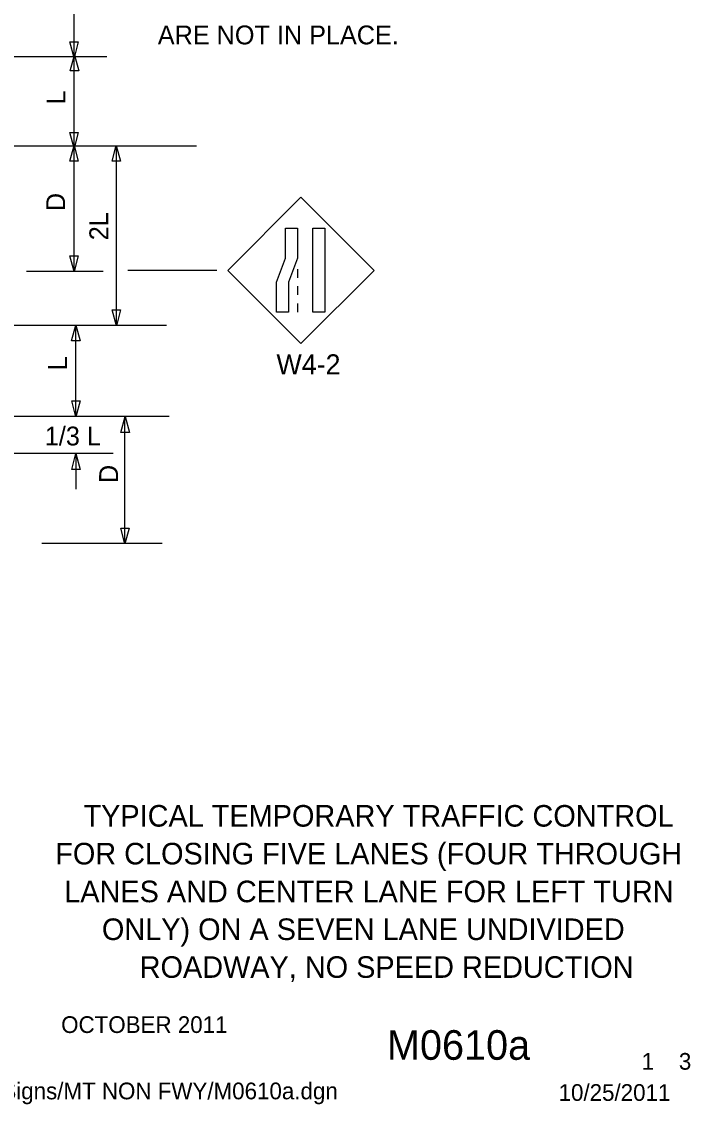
# Model space of a CAD drawing. Extents: x 16646 to 19498, y 2812 to 4437.
# Drawn here: x 17147.1 to 17395.3, y 3023.5 to 3425.5 of the extents above; entities that cross this region are included whole.
import ezdxf

# ---------------------------------------------------------------- set-up
doc = ezdxf.new("R2010")
doc.units = 0
for name, color, linetype in [('BORDER', 7, 'Continuous'), ('BORDER_SIGNAL_WO', 7, 'Continuous'), ('TRAFFIC_SIGNS_PR', 7, 'Continuous'), ('TYPICAL_TEXT_DIMEN_PR', 7, 'Continuous')]:
    doc.layers.add(name, color=color, linetype=linetype)

msp = doc.modelspace()

# ---------------------------------------------------------------- linework, layer by layer
at = {"layer": 'TRAFFIC_SIGNS_PR'}
for p, q in [((17250.74, 3360.24), (17223.58, 3333.09)), ((17277.89, 3333.09), (17250.74, 3360.24)), ((17223.58, 3333.09), (17250.74, 3305.93)), ((17249.49, 3333.58), (17249.49, 3330.38)), ((17250.74, 3305.93), (17277.89, 3333.09)), ((17249.49, 3327.18), (17249.49, 3323.98)), ((17249.49, 3320.78), (17249.49, 3317.58))]:
    msp.add_line(p, q, dxfattribs=at)
for points in [[(17249.49, 3348.82), (17249.49, 3337.64), (17246.14, 3328.76), (17246.14, 3317.58), (17241.65, 3317.58), (17241.65, 3328.76), (17244.99, 3337.64), (17244.99, 3348.82)], [(17259.62, 3348.82), (17259.62, 3317.58), (17255.13, 3317.58), (17255.13, 3348.82)]]:
    msp.add_lwpolyline(points, close=True, dxfattribs=at)
at = {"layer": 'TYPICAL_TEXT_DIMEN_PR'}
for p, q in [((17166.57, 3333.09), (17166.57, 3445.09)), ((17166.57, 3412.05), (17165, 3417.91)), ((17165, 3417.91), (17166.57, 3417.91)), ((17166.57, 3417.91), (17168.14, 3417.91)), ((17168.14, 3417.91), (17166.57, 3412.05)), ((17165.18, 3407.2), (17166.75, 3413.06)), ((17166.75, 3413.06), (17168.32, 3407.2)), ((17178.73, 3412.43), (17089.36, 3412.43)), ((17166.75, 3407.2), (17165.18, 3407.2)), ((17168.32, 3407.2), (17166.75, 3407.2)), ((17166.57, 3378.49), (17165, 3384.35)), ((17165, 3384.35), (17166.57, 3384.35)), ((17166.57, 3384.35), (17168.14, 3384.35)), ((17168.14, 3384.35), (17166.57, 3378.49)), ((17212.03, 3379.22), (17085.88, 3379.22)), ((17165, 3373.64), (17166.57, 3379.5)), ((17166.57, 3379.5), (17168.14, 3373.64)), ((17180.68, 3373.61), (17182.25, 3379.47)), ((17182.18, 3378.94), (17182.18, 3312.77)), ((17182.25, 3379.47), (17183.82, 3373.61)), ((17166.57, 3373.64), (17165, 3373.64)), ((17168.14, 3373.64), (17166.57, 3373.64)), ((17182.25, 3373.61), (17180.68, 3373.61)), ((17183.82, 3373.61), (17182.25, 3373.61)), ((17166.57, 3332.69), (17165, 3338.55)), ((17165, 3338.55), (17166.57, 3338.55)), ((17166.57, 3338.55), (17168.14, 3338.55)), ((17168.14, 3338.55), (17166.57, 3332.69)), ((17177.37, 3332.69), (17148.92, 3332.69)), ((17219.58, 3333.03), (17186.57, 3333.03)), ((17182.26, 3312.57), (17180.69, 3318.43)), ((17180.69, 3318.43), (17182.26, 3318.43)), ((17182.26, 3318.43), (17183.83, 3318.43)), ((17183.83, 3318.43), (17182.26, 3312.57)), ((17200.84, 3312.69), (17067.65, 3312.69)), ((17165.66, 3306.93), (17167.23, 3312.8)), ((17167.23, 3312.8), (17168.8, 3306.93)), ((17167.15, 3312.38), (17167.15, 3278.99)), ((17167.23, 3306.93), (17165.66, 3306.93)), ((17168.8, 3306.93), (17167.23, 3306.93)), ((17167.28, 3278.76), (17165.71, 3284.62)), ((17165.71, 3284.62), (17167.28, 3284.62)), ((17167.28, 3284.62), (17168.85, 3284.62)), ((17168.85, 3284.62), (17167.28, 3278.76)), ((17201.92, 3278.8), (17124.22, 3278.8)), ((17183.94, 3272.93), (17185.51, 3278.8)), ((17185.45, 3232.02), (17185.45, 3278.35)), ((17185.51, 3278.8), (17187.08, 3272.93)), ((17185.51, 3272.93), (17183.94, 3272.93)), ((17187.08, 3272.93), (17185.51, 3272.93)), ((17181.03, 3265.05), (17124.07, 3265.05)), ((17165.71, 3259.18), (17167.28, 3265.05)), ((17167.21, 3264.9), (17167.21, 3251.9)), ((17167.28, 3265.05), (17168.85, 3259.18)), ((17167.28, 3259.18), (17165.71, 3259.18)), ((17168.85, 3259.18), (17167.28, 3259.18)), ((17185.46, 3231.58), (17183.89, 3237.44)), ((17183.89, 3237.44), (17185.46, 3237.44)), ((17185.46, 3237.44), (17187.03, 3237.44)), ((17187.03, 3237.44), (17185.46, 3231.58)), ((17199.26, 3231.7), (17154.59, 3231.7))]:
    msp.add_line(p, q, dxfattribs=at)

# ---------------------------------------------------------------- texts
at = {"layer": 'BORDER'}
for s, p in [('TYPICAL TEMPORARY TRAFFIC CONTROL', (17170.08, 3126.58)), ('FOR CLOSING FIVE LANES (FOUR THROUGH', (17159.58, 3112.54)), ('LANES AND CENTER LANE FOR LEFT TURN', (17162.92, 3098.5)), ('ONLY) ON A SEVEN LANE UNDIVIDED', (17176.9, 3084.47)), ('ROADWAY, NO SPEED REDUCTION', (17190.92, 3070.43))]:
    msp.add_text(s, height=8.0099, dxfattribs=at).set_placement(p)
at = {"layer": 'BORDER_SIGNAL_WO'}
for s, height, p in [('    OCTOBER 2011    ', 6.2, (17152.56, 3049.96)), ('    M0610a   ', 11, (17266.34, 3040)), (' 1    3 ', 6.2, (17374.92, 3036.32)), ('PW RD/TS/Typicals/Signs/MT NON FWY/M0610a.dgn    ', 6.2, (17064.03, 3025.33)), ('10/25/2011    ', 6.2, (17346.4, 3024.75))]:
    msp.add_text(s, height=height, dxfattribs=at).set_placement(p)
at = {"layer": 'TRAFFIC_SIGNS_PR'}
for s, height, p in [('ARE NOT IN PLACE.', 7, (17197.64, 3417.01)), ('W4-2', 7.44, (17241.69, 3294.49))]:
    msp.add_text(s, height=height, dxfattribs=at).set_placement(p)
at = {"layer": 'TYPICAL_TEXT_DIMEN_PR'}
for s, p in [('L', (17163.35, 3394.71)), ('D', (17163.25, 3355.1)), ('2L', (17179.25, 3344.28)), ('L', (17163.95, 3296.01)), ('D', (17182.88, 3254.14))]:
    msp.add_text(s, height=7, rotation=90, dxfattribs=at).set_placement(p)
msp.add_text('1/3 L', height=7, dxfattribs=at).set_placement((17155.71, 3268.1))

doc.saveas('drawing.dxf')
